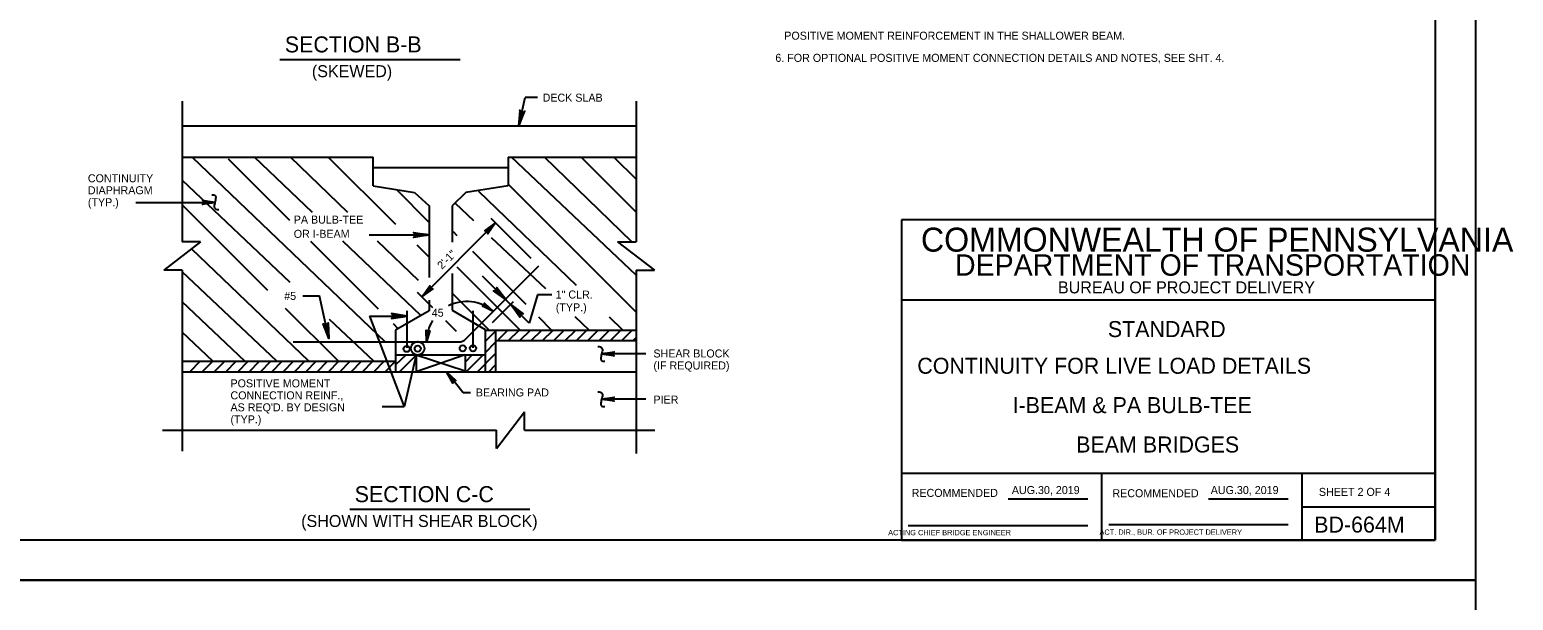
# Model space of a CAD drawing. Extents: x 639980 to 641204, y 298038 to 300414.
# Drawn here: x 640280 to 640836, y 299218 to 299432 of the extents above; entities that cross this region are included whole.
import ezdxf

# ---------------------------------------------------------------- set-up
doc = ezdxf.new("R2010")
doc.units = 0
for name, color, linetype in [('1', 7, 'Continuous'), ('2', 7, 'Continuous'), ('3', 7, 'Continuous'), ('PLT-BNDY', 7, 'Continuous')]:
    doc.layers.add(name, color=color, linetype=linetype)

msp = doc.modelspace()

# ---------------------------------------------------------------- linework, layer by layer
at = {"layer": '1'}
for points in [[(640350.46, 299364.63), (640349.5, 299364.71), (640348.98, 299365.2), (640348.77, 299366.12), (640349.03, 299366.98), (640349.21, 299367.89), (640349.37, 299368.81), (640349.26, 299369.72), (640348.59, 299370.11), (640347.86, 299370.11)], [(640492.51, 299313.36), (640493.47, 299313.28), (640494, 299312.79), (640494.21, 299311.87), (640493.94, 299311.01), (640493.76, 299310.1), (640493.61, 299309.18), (640493.71, 299308.27), (640494.39, 299307.88), (640495.12, 299307.88)], [(640492.51, 299296.41), (640493.47, 299296.33), (640494, 299295.84), (640494.21, 299294.92), (640493.94, 299294.06), (640493.76, 299293.15), (640493.61, 299292.23), (640493.71, 299291.32), (640494.39, 299290.93), (640495.12, 299290.93)]]:
    msp.add_spline(points, degree=3, dxfattribs=at)
at = {"layer": '2'}
for p, q in [((640806.31, 299804.78), (640806.31, 299240.78)), ((640440.85, 299420.82), (640373.35, 299420.82)), ((640336.68, 299405.34), (640336.68, 299352.54)), ((640462.9, 299396.04), (640465.24, 299406.64)), ((640469.86, 299406.64), (640465.24, 299406.64)), ((640506.8, 299405.34), (640506.8, 299352.54)), ((640336.68, 299396.04), (640506.8, 299396.04)), ((640336.68, 299384.34), (640408.23, 299384.34)), ((640340.43, 299384.34), (640412.76, 299315.14)), ((640353.99, 299383.68), (640376.97, 299360.7)), ((640385.58, 299363.63), (640363.83, 299384.34)), ((640398.78, 299363.63), (640377.33, 299384.34)), ((640416.82, 299359.15), (640391.43, 299384.34)), ((640408.23, 299380.44), (640408.23, 299384.34)), ((640458.93, 299384.34), (640506.8, 299384.34)), ((640458.93, 299384.34), (640458.93, 299380.44)), ((640506.8, 299340.16), (640460.13, 299384.34)), ((640505.27, 299352.54), (640472.43, 299384.34)), ((640486.23, 299384.34), (640506.8, 299363.76)), ((640498.53, 299384.34), (640506.8, 299376.06)), ((640377.22, 299337.41), (640336.68, 299375.7)), ((640408.23, 299380.44), (640458.93, 299380.44)), ((640408.23, 299373.54), (640408.23, 299380.44)), ((640458.93, 299380.44), (640458.93, 299373.54)), ((640408.23, 299373.54), (640423.83, 299371.14)), ((640429.23, 299359.78), (640417.06, 299372.18)), ((640423.83, 299371.14), (640429.23, 299366.04)), ((640443.03, 299371.14), (640437.93, 299366.04)), ((640458.93, 299373.54), (640443.03, 299371.14)), ((640484.47, 299336.25), (640447.83, 299371.44)), ((640506.8, 299326.26), (640458.93, 299374.14)), ((640319.31, 299367.38), (640349.11, 299367.38)), ((640368.79, 299334.38), (640336.68, 299366.49)), ((640429.23, 299366.04), (640429.23, 299339.19)), ((640437.93, 299366.04), (640437.93, 299352.42)), ((640445.99, 299360.45), (640439.13, 299366.94)), ((640426.72, 299332.21), (640454.06, 299359.54)), ((640467.53, 299346.36), (640452.54, 299361.34)), ((640806.31, 299360.78), (640606.31, 299360.78)), ((640606.31, 299360.78), (640606.31, 299240.78)), ((640806.31, 299240.78), (640806.31, 299360.78)), ((640406.83, 299355.19), (640429.23, 299355.19)), ((640438.23, 299356.44), (640439.66, 299355)), ((640472.93, 299334.95), (640452.66, 299354.13)), ((640343.58, 299352.54), (640329.78, 299342.04)), ((640343.58, 299352.54), (640336.68, 299352.54)), ((640384.23, 299307.84), (640340.27, 299350.03)), ((640384.77, 299352.9), (640410.15, 299327.52)), ((640426.17, 299324.99), (640396.86, 299352.9)), ((640425.27, 299338.07), (640409.9, 299352.9)), ((640429.23, 299346.84), (640424.74, 299351.29)), ((640445.54, 299349.13), (640465.46, 299329.2)), ((640499.9, 299352.54), (640506.8, 299352.54)), ((640499.9, 299352.54), (640513.7, 299342.04)), ((640336.68, 299342.04), (640329.78, 299342.04)), ((640336.68, 299342.04), (640336.68, 299274.17)), ((640439.69, 299343.28), (640463.43, 299319.54)), ((640443, 299316.22), (640470.33, 299343.55)), ((640506.8, 299342.04), (640506.8, 299273.27)), ((640506.8, 299342.04), (640513.7, 299342.04)), ((640372.23, 299307.84), (640336.68, 299341.4)), ((640437.93, 299340.72), (640437.93, 299327.04)), ((640459.8, 299329.11), (640449.21, 299339.7)), ((640381.89, 299332.4), (640388.18, 299332.4)), ((640391.71, 299316.41), (640388.18, 299332.4)), ((640430.64, 299327.86), (640424.85, 299333.65)), ((640429.23, 299330.8), (640429.23, 299326.74)), ((640437.93, 299333.34), (640451.73, 299319.54)), ((640469.9, 299332.68), (640466.72, 299322.18)), ((640475.19, 299332.68), (640469.9, 299332.68)), ((640806.31, 299330.78), (640606.31, 299330.78)), ((640360.23, 299307.84), (640336.68, 299330.07)), ((640395.33, 299307.84), (640375.49, 299327.67)), ((640429.23, 299326.74), (640416.63, 299319.54)), ((640421, 299312.85), (640421, 299326.74)), ((640437.93, 299327.04), (640450.23, 299319.72)), ((640445.74, 299312.85), (640445.74, 299326.74)), ((640460.79, 299330.11), (640452.87, 299322.19)), ((640466.72, 299322.18), (640459.8, 299329.11)), ((640408.53, 299307.84), (640391.89, 299323.55)), ((640406.86, 299324.8), (640421, 299324.8)), ((640406.86, 299324.8), (640419.89, 299290.79)), ((640415.72, 299321.95), (640417.58, 299320.09)), ((640439.55, 299318.95), (640435.55, 299322.95)), ((640470.23, 299324.44), (640475.13, 299319.54)), ((640489.21, 299319.54), (640484.03, 299324.44)), ((640501.88, 299319.54), (640496.81, 299324.4)), ((640348.23, 299307.84), (640336.68, 299318.74)), ((640378.3, 299315.14), (640440.39, 299315.14)), ((640416.63, 299319.54), (640416.63, 299310.24)), ((640450.23, 299319.54), (640506.8, 299319.54)), ((640450.23, 299319.54), (640450.23, 299319.54)), ((640450.23, 299319.54), (640450.23, 299310.24)), ((640450.23, 299311.05), (640454.13, 299314.95)), ((640450.57, 299315.64), (640454.47, 299319.54)), ((640454.13, 299319.54), (640454.13, 299303.94)), ((640454.13, 299315.64), (640506.8, 299315.64)), ((640455.21, 299316.04), (640458.71, 299319.54)), ((640459.05, 299315.64), (640462.95, 299319.54)), ((640463.3, 299315.64), (640467.2, 299319.54)), ((640467.54, 299315.64), (640471.44, 299319.54)), ((640471.78, 299315.64), (640475.68, 299319.54)), ((640476.02, 299315.64), (640479.92, 299319.54)), ((640480.27, 299315.64), (640484.17, 299319.54)), ((640484.51, 299315.64), (640488.41, 299319.54)), ((640488.75, 299315.64), (640492.65, 299319.54)), ((640492.99, 299315.64), (640496.89, 299319.54)), ((640497.24, 299315.64), (640501.14, 299319.54)), ((640501.48, 299315.64), (640505.38, 299319.54)), ((640505.72, 299315.64), (640506.8, 299316.72)), ((640416.63, 299310.24), (640450.23, 299310.24)), ((640420.6, 299310.24), (640416.63, 299306.53)), ((640416.63, 299310.24), (640416.63, 299303.94)), ((640424.13, 299309.94), (640418.13, 299303.94)), ((640424.43, 299310.2), (640419.89, 299290.79)), ((640424.43, 299310.24), (640424.43, 299303.94)), ((640424.43, 299310.24), (640442.73, 299304.24)), ((640442.73, 299310.24), (640424.43, 299303.94)), ((640442.73, 299310.24), (640442.73, 299304.24)), ((640445.43, 299310.24), (640442.73, 299307.54)), ((640449.3, 299310.03), (640443.3, 299304.03)), ((640447.35, 299303.94), (640454.13, 299310.71)), ((640450.23, 299310.24), (640450.23, 299303.94)), ((640510.42, 299310.61), (640493.86, 299310.61)), ((640336.68, 299307.84), (640416.63, 299307.84)), ((640336.68, 299303.94), (640454.13, 299303.94)), ((640339.6, 299303.94), (640343.5, 299307.84)), ((640344.26, 299303.94), (640348.16, 299307.84)), ((640348.74, 299303.94), (640352.64, 299307.84)), ((640353.11, 299303.94), (640357.01, 299307.84)), ((640357.52, 299303.94), (640361.42, 299307.84)), ((640361.81, 299303.94), (640365.71, 299307.84)), ((640366.06, 299303.94), (640369.96, 299307.84)), ((640370.3, 299303.94), (640374.2, 299307.84)), ((640374.54, 299303.94), (640378.44, 299307.84)), ((640378.78, 299303.94), (640382.68, 299307.84)), ((640383.03, 299303.94), (640386.93, 299307.84)), ((640387.27, 299303.94), (640391.17, 299307.84)), ((640391.51, 299303.94), (640395.41, 299307.84)), ((640395.76, 299303.94), (640399.66, 299307.84)), ((640400, 299303.94), (640403.9, 299307.84)), ((640404.24, 299303.94), (640408.14, 299307.84)), ((640408.48, 299303.94), (640412.38, 299307.84)), ((640412.73, 299303.94), (640416.63, 299307.84)), ((640416.63, 299307.84), (640416.63, 299307.84)), ((640424.43, 299307.54), (640424.43, 299307.54)), ((640442.02, 299295.97), (640435.78, 299303.94)), ((640442.73, 299307.54), (640442.73, 299307.54)), ((640451.6, 299303.94), (640454.13, 299306.47)), ((640454.13, 299303.94), (640506.8, 299303.94)), ((640444.79, 299295.97), (640442.02, 299295.97)), ((640510.42, 299293.66), (640493.86, 299293.66)), ((640419.89, 299290.79), (640411.66, 299290.79)), ((640454.51, 299275.13), (640465.01, 299288.93)), ((640465.01, 299282.03), (640465.01, 299288.93)), ((640329.36, 299282.03), (640454.51, 299282.03)), ((640454.51, 299275.13), (640454.51, 299282.03)), ((640465.01, 299282.03), (640513.86, 299282.03)), ((640806.31, 299265.78), (640606.31, 299265.78)), ((640681.31, 299240.78), (640681.31, 299265.78)), ((640756.31, 299265.78), (640756.31, 299240.78)), ((640646.27, 299256.28), (640676.04, 299256.28)), ((640721.27, 299256.28), (640751.18, 299256.28)), ((640756.31, 299253.28), (640806.31, 299253.28)), ((640467.01, 299252.31), (640399.51, 299252.31)), ((640608.81, 299246.28), (640676.04, 299246.28)), ((640683.93, 299246.66), (640751.18, 299246.66)), ((640806.31, 299240.78), (640020.31, 299240.78)), ((640606.31, 299240.78), (640806.31, 299240.78))]:
    msp.add_line(p, q, dxfattribs=at)
for points in [[(640463.41, 299401.6), (640463.76, 299401.31), (640462.9, 299396.04), (640463.41, 299401.6), (640463.24, 299401.92), (640462.9, 299396.04), (640464.3, 299401.18), (640464.73, 299401.29), (640462.9, 299396.04), (640465.06, 299401.52), (640464.73, 299401.29)], [(640450.44, 299356.73), (640450.8, 299356.62), (640454.06, 299359.54), (640450.44, 299356.73), (640450.14, 299356.71), (640454.06, 299359.54), (640451.12, 299356.3), (640451.24, 299355.96), (640454.06, 299359.54), (640451.22, 299355.63), (640451.24, 299355.96)], [(640423.69, 299355.88), (640423.9, 299355.48), (640429.23, 299355.19), (640423.69, 299355.88), (640423.41, 299356.13), (640429.23, 299355.19), (640423.9, 299354.93), (640423.71, 299354.53), (640429.23, 299355.19), (640423.41, 299354.26), (640423.71, 299354.53)], [(640430.34, 299335.01), (640429.99, 299335.13), (640426.72, 299332.21), (640430.34, 299335.01), (640430.64, 299335.04), (640426.72, 299332.21), (640429.66, 299335.45), (640429.54, 299335.79), (640426.72, 299332.21), (640429.56, 299336.12), (640429.54, 299335.79)], [(640415.47, 299324.11), (640415.67, 299324.51), (640421, 299324.8), (640415.47, 299324.11), (640415.18, 299323.87), (640421, 299324.8), (640415.68, 299325.07), (640415.48, 299325.46), (640421, 299324.8), (640415.18, 299325.73), (640415.48, 299325.46)], [(640450.06, 299329.33), (640450.02, 299329), (640453.2, 299326.66), (640450.06, 299329.33), (640449.98, 299329.59), (640453.2, 299326.66), (640449.8, 299328.65), (640449.52, 299328.48), (640453.2, 299326.66), (640449.23, 299328.44), (640449.52, 299328.48)], [(640391.2, 299321.97), (640390.85, 299321.68), (640391.71, 299316.41), (640391.2, 299321.97), (640391.37, 299322.3), (640391.71, 299316.41), (640390.31, 299321.56), (640389.88, 299321.66), (640391.71, 299316.41), (640389.55, 299321.9), (640389.88, 299321.66)], [(640429.29, 299319.12), (640428.97, 299319.01), (640428.25, 299315.13), (640429.29, 299319.12), (640429.49, 299319.3), (640428.25, 299315.13), (640428.57, 299319.06), (640428.29, 299319.24), (640428.25, 299315.13), (640428.13, 299319.48), (640428.29, 299319.24)]]:
    msp.add_lwpolyline(points, dxfattribs=at)
for centre, radius in [((640424.97, 299312.68), 2.54), ((640420.84, 299312.49), 1.16), ((640425, 299312.57), 1.16), ((640441.87, 299312.71), 1.16), ((640445.72, 299312.71), 1.16)]:
    msp.add_circle(centre, radius, dxfattribs=at)
for centre, radius, start, end in [((640443.41, 299315.1), 15.15, 49.7549, 117.1497), ((640443.41, 299315.1), 15.15, 148.1371, 179.8636), ((640440.69, 299318.14), 3, 264.2163, 320.132)]:
    msp.add_arc(centre, radius, start, end, dxfattribs=at)
at = {"layer": '3'}
for points in [[(640344.57, 299367.95), (640344.74, 299367.62), (640349.11, 299367.38), (640344.57, 299367.95), (640344.34, 299368.15), (640349.11, 299367.38), (640344.74, 299367.17), (640344.58, 299366.84), (640349.11, 299367.38), (640344.34, 299366.62), (640344.58, 299366.84)], [(640454.72, 299335.16), (640454.59, 299334.74), (640458.09, 299330.82), (640454.72, 299335.16), (640454.69, 299335.53), (640458.09, 299330.82), (640454.2, 299334.35), (640453.79, 299334.21), (640458.09, 299330.82), (640453.4, 299334.23), (640453.79, 299334.21)], [(640463.19, 299324.72), (640463.32, 299325.15), (640459.82, 299329.07), (640463.19, 299324.72), (640463.21, 299324.36), (640459.82, 299329.07), (640463.71, 299325.54), (640464.12, 299325.68), (640459.82, 299329.07), (640464.51, 299325.65), (640464.12, 299325.68)], [(640498.4, 299310.04), (640498.23, 299310.37), (640493.86, 299310.61), (640498.4, 299310.04), (640498.63, 299309.84), (640493.86, 299310.61), (640498.23, 299310.82), (640498.39, 299311.15), (640493.86, 299310.61), (640498.64, 299311.37), (640498.39, 299311.15)], [(640438.13, 299300.01), (640438.28, 299300.35), (640435.78, 299303.94), (640438.13, 299300.01), (640438.11, 299299.7), (640435.78, 299303.94), (640438.64, 299300.63), (640439, 299300.7), (640435.78, 299303.94), (640439.32, 299300.64), (640439, 299300.7)], [(640498.4, 299293.09), (640498.23, 299293.42), (640493.86, 299293.66), (640498.4, 299293.09), (640498.63, 299292.89), (640493.86, 299293.66), (640498.23, 299293.88), (640498.39, 299294.2), (640493.86, 299293.66), (640498.64, 299294.42), (640498.39, 299294.2)]]:
    msp.add_lwpolyline(points, dxfattribs=at)
at = {"layer": 'PLT-BNDY'}
for points in [[(639980.31, 299819.78), (640821.31, 299819.78), (640821.31, 299225.78), (639980.31, 299225.78)], [(639980.31, 299225.78), (640821.31, 299225.78), (640821.31, 298631.78), (639980.31, 298631.78)]]:
    msp.add_lwpolyline(points, close=True, dxfattribs=at)

# ---------------------------------------------------------------- texts
at = {"layer": '2'}
for s, height, p in [('   POSITIVE MOMENT REINFORCEMENT IN THE SHALLOWER BEAM.', 3, (640559, 299428.33)), ('SECTION B-B', 6, (640375.19, 299423.57)), ('6. FOR OPTIONAL POSITIVE MOMENT CONNECTION DETAILS AND NOTES, SEE SHT. 4.', 3, (640559, 299420.03)), ('COMMONWEALTH OF PENNSYLVANIA', 9, (640613.56, 299348.91)), ('DEPARTMENT OF TRANSPORTATION', 8.0002, (640626.31, 299339.91)), ('BUREAU OF PROJECT DELIVERY', 4.5, (640664.9, 299333.28)), ('STANDARD', 6, (640683.6, 299316.91)), ('CONTINUITY FOR LIVE LOAD DETAILS', 6, (640612.19, 299303.16)), ('I-BEAM & PA BULB-TEE', 6, (640647.91, 299288.41)), ('BEAM BRIDGES', 6, (640671.73, 299273.66)), ('SECTION C-C', 6, (640401.36, 299255.06)), ('RECOMMENDED', 3, (640610.08, 299257.03)), ('AUG.30, 2019', 3, (640647.61, 299258.09)), ('RECOMMENDED', 3, (640685.3, 299256.91)), ('AUG.30, 2019', 3, (640722.15, 299258.09)), ('SHEET 2 OF 4', 3, (640762.68, 299257.41)), ('BD-664M', 6, (640760.93, 299243.66)), ('       ACTING CHIEF BRIDGE ENGINEER', 2.0002, (640595.9, 299242.66)), ('   ACT. DIR., BUR. OF PROJECT DELIVERY', 2.0002, (640678.16, 299242.83))]:
    msp.add_text(s, height=height, dxfattribs=at).set_placement(p)
msp.add_text('2\'-1"', height=2.999, rotation=45, dxfattribs=at).set_placement((640434.08, 299342.06))
at = {"layer": '3'}
for s, height, p in [('(SKEWED)', 4.5, (640385.32, 299414.29)), ('DECK SLAB', 2.997, (640471.79, 299405.11)), ('CONTINUITY', 2.997, (640301.37, 299374.91)), ('DIAPHRAGM', 2.997, (640301.37, 299370.42)), ('(TYP.)', 2.997, (640301.37, 299365.92)), ('PA BULB-TEE', 2.9969, (640378.53, 299359.42)), ('OR I-BEAM', 2.997, (640378.53, 299354.1)), ('#5', 2.997, (640374.95, 299330.82)), ('1" CLR.', 2.997, (640476.68, 299331.36)), ('45', 2.999, (640430.24, 299324.53)), ('(TYP.)', 2.997, (640476.73, 299326.56)), ('SHEAR BLOCK', 2.999, (640513.31, 299309.27)), ('(IF REQUIRED)', 2.999, (640513.31, 299304.77)), ('POSITIVE MOMENT', 2.9969, (640354.82, 299298.08)), ('BEARING PAD', 2.9969, (640446.77, 299294.66)), ("AS REQ'D. BY DESIGN", 2.9969, (640354.82, 299289.09)), ('CONNECTION REINF.,', 2.9969, (640354.82, 299293.58)), ('PIER', 2.999, (640513.31, 299291.99)), ('(TYP.)', 2.997, (640354.82, 299284.59)), ('(SHOWN WITH SHEAR BLOCK)', 4.5, (640381.31, 299245.75))]:
    msp.add_text(s, height=height, dxfattribs=at).set_placement(p)

doc.saveas('drawing.dxf')
